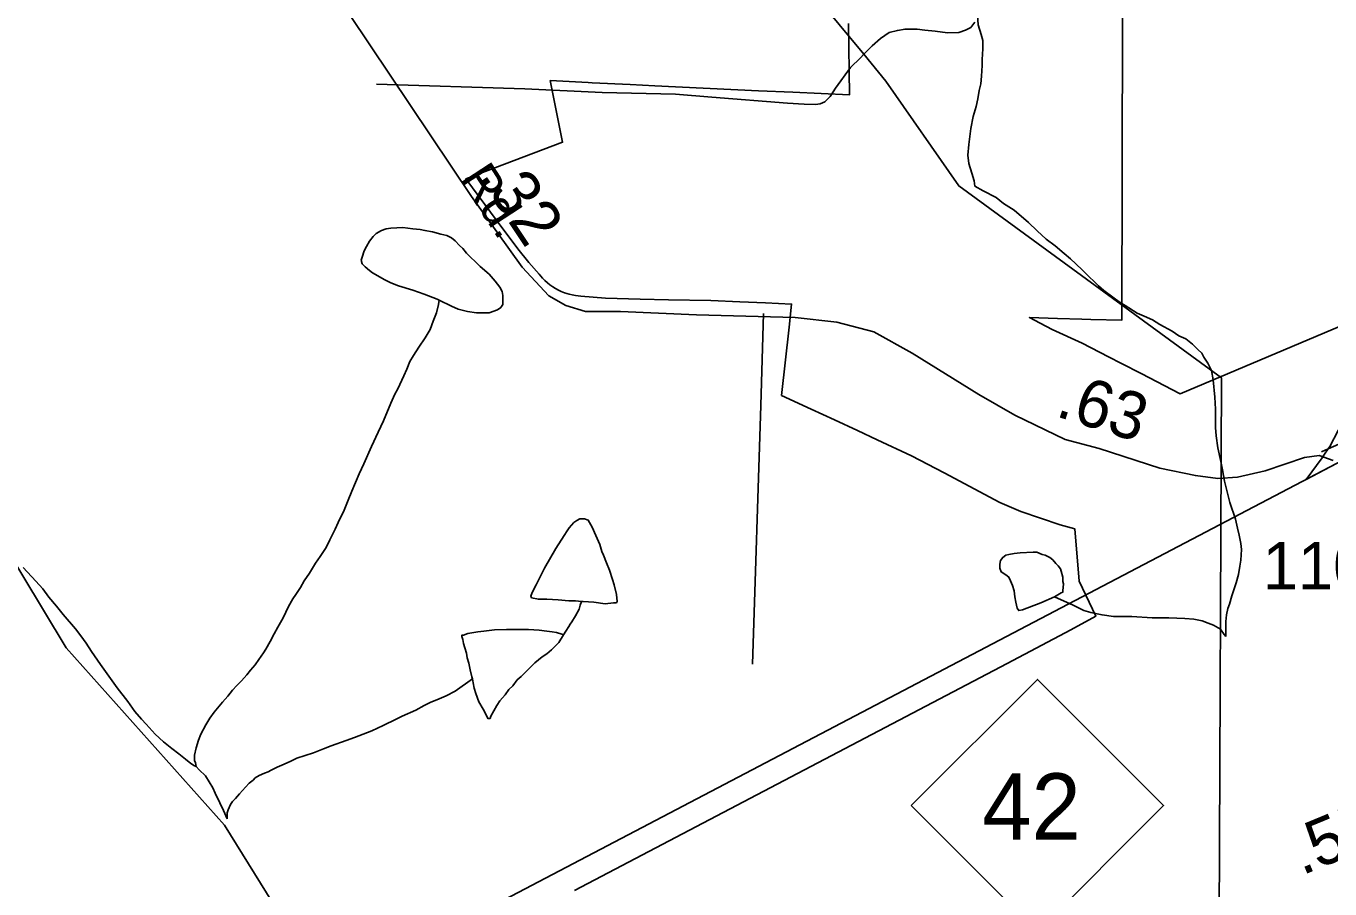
# Model space of a CAD drawing. Extents: x 2001466 to 2224147, y 644118 to 847247.
# Drawn here: x 2052213 to 2055654, y 667157 to 669433 of the extents above; entities that cross this region are included whole.
import ezdxf

# ---------------------------------------------------------------- set-up
doc = ezdxf.new("R2010")
doc.units = 0
for name, color, linetype in [('Exist Boundary Political City Limit New', 7, 'Continuous'), ('Exist Hydrographic Creek Single Shore', 7, 'Continuous'), ('Exist Hydrographic Misc Water Feature', 7, 'Continuous'), ('Exist Railroad Mainline', 7, 'Continuous'), ('Exist Railroad Siding', 7, 'Continuous'), ('Exist Road Non-System Type 51', 7, 'Continuous'), ('Exist Road Primary NC Service Mileage Hundredths English Label', 7, 'Continuous'), ('Exist Road Primary NC Shield CELL', 7, 'Continuous'), ('Exist Road Primary NC Shield Number Label', 7, 'Continuous'), ('Exist Road Secondary Mileage Hundredths English Label', 7, 'Continuous'), ('Exist Road Secondary Type 51 Attributed', 7, 'Continuous'), ('Exist Road Secondary Type 51 Label', 7, 'Continuous'), ('Exist Road Secondary Type 51 Number Label', 7, 'Continuous'), ('Map Preparation Boundary City Limit Buffer Line', 7, 'Continuous')]:
    doc.layers.add(name, color=color, linetype=linetype)

msp = doc.modelspace()

# ---------------------------------------------------------------- linework, layer by layer
at = {"layer": 'Exist Boundary Political City Limit New'}
for points in [[(2055701.8, 668649.8), (2055258.9, 668463.2), (2055156.2, 668516.1), (2055104.1, 668543), (2055069.6, 668560.8), (2055000, 668596.4), (2054921.2, 668632.2), (2054889.4, 668649.1), (2054860.8, 668663.9), (2054935.2, 668661.9), (2054999.6, 668660.2), (2055023.4, 668659.4), (2055104.4, 668657.1), (2055105.8, 669052.5), (2055106.2, 669457.1)], [(2054383.1, 669440), (2054385.9, 669251.4), (2054237, 669258.4), (2054146, 669262.7), (2053872, 669275.7), (2053807.2, 669278.8), (2053707.2, 669283.6), (2053696.8, 669284), (2053596.4, 669289.1), (2053629.1, 669126.5), (2053373.8, 669030.4), (2053456.2, 668918.2), (2053510.9, 668845.7), (2053540.2, 668809.4), (2053566.8, 668778.3), (2053576, 668767.7), (2053582, 668761.8), (2053588.8, 668755.8), (2053595.5, 668750.5), (2053602.8, 668745.5), (2053610.1, 668740.9), (2053617.8, 668736.7), (2053625.5, 668733.1), (2053633.9, 668729.7), (2053646.2, 668725.8), (2053654.6, 668723.8), (2053663.2, 668722.2), (2053676.9, 668720.7), (2053741.8, 668715), (2053833.8, 668712.4), (2053908.2, 668710.8), (2054020.4, 668709.4), (2054096.8, 668705.5), (2054164.5, 668703.1), (2054233.2, 668699.8), (2054226.8, 668638.8), (2054207, 668458.8), (2054285.2, 668422.3), (2054346.1, 668394.1), (2054407.1, 668365.7), (2054459, 668341.6), (2054549.8, 668299.6), (2054635.6, 668254.1), (2054782.9, 668176.1), (2054838.4, 668152.8), (2054942.1, 668117.1), (2054980.4, 668106.4), (2054991.9, 667968.2), (2055036.6, 667876.4), (2054970, 667839.8), (2054801.8, 667751.5), (2053660.4, 667152.6)]]:
    msp.add_lwpolyline(points, dxfattribs=at)
at = {"layer": 'Exist Hydrographic Creek Single Shore'}
msp.add_lwpolyline([(2053017.7, 666872.7), (2052736.4, 667325.2), (2052319.3, 667793), (2052143.4, 668082), (2051868.4, 668350), (2051451.4, 668630.9), (2051117.3, 668781.9), (2050292.4, 668952.9), (2050134.3, 669028.3), (2049975.4, 669271), (2049847.4, 669402.6)], dxfattribs=at)
at = {"layer": 'Exist Hydrographic Misc Water Feature'}
for points in [[(2054423.7, 669358.6), (2054098.4, 669751.6), (2053823.4, 669954), (2053598.5, 670168.5), (2053547.4, 670310.7), (2053489.4, 670528.5), (2053363.5, 670609.7), (2052988.4, 670633.8)], [(2054761.9, 669556.8), (2054739.8, 669514.7), (2054729.9, 669490.7), (2054726, 669476.7), (2054724, 669462.7), (2054726, 669436.7), (2054734, 669410.7), (2054738.1, 669394.8), (2054738.1, 669372.8), (2054736.3, 669344.8), (2054736.3, 669328.8), (2054734.2, 669300.8), (2054732.4, 669280.8), (2054728.3, 669262.8), (2054724.4, 669240.8), (2054720.5, 669220.8), (2054712.5, 669194.7), (2054706.6, 669162.7), (2054700.6, 669120.7), (2054698.8, 669092.7), (2054700.8, 669070.7), (2054708.8, 669044.8), (2054715, 669024.8), (2054716.8, 669010.8)], [(2055335.1, 668528.9), (2054674.4, 669011.5), (2054482.4, 669287.7), (2054423.7, 669358.6)], [(2054716.8, 669010.8), (2054739, 668998.8), (2054772.8, 668980.9), (2054792.9, 668964.9), (2054820.8, 668947), (2054858.9, 668915.1), (2054881.1, 668893.1), (2054905.1, 668871.2), (2054929, 668853.2), (2054953, 668833.3), (2054969, 668819.3), (2054983.2, 668805.4), (2055001.2, 668789.4), (2055017.2, 668773.4), (2055033.2, 668757.4), (2055043.3, 668747.5), (2055057.2, 668735.5), (2055081.2, 668717.5), (2055097.4, 668705.6), (2055113.4, 668695.6), (2055145.4, 668675.7), (2055163.4, 668667.7), (2055185.4, 668657.7), (2055205.5, 668645.8), (2055237.4, 668627.8), (2055255.5, 668615.8), (2055273.5, 668607.9), (2055291.6, 668593.9), (2055305.5, 668580), (2055315.6, 668570), (2055321.5, 668560), (2055331.6, 668544.1), (2055341.6, 668524), (2055345.5, 668500), (2055349.8, 668454.1), (2055351.7, 668422.1), (2055351.9, 668398.1), (2055351.9, 668374.1), (2055353.9, 668352.1), (2055358, 668320.1), (2055366, 668284.1), (2055370.1, 668262.2), (2055376.1, 668232.2), (2055390.2, 668176.2), (2055404.4, 668132.2), (2055410.3, 668108.2), (2055414.4, 668090.2), (2055418.5, 668068.3), (2055420.6, 668052.3), (2055418.5, 668024.3), (2055416.5, 668008.3), (2055412.6, 667986.3), (2055406.6, 667964.3), (2055398.6, 667940.2), (2055394.7, 667930.2), (2055388.8, 667908.3), (2055384.7, 667896.3), (2055380.8, 667880.2), (2055379.6, 667862.3), (2055379.4, 667852.2), (2055379.6, 667862.3), (2055379.4, 667852.2), (2055378.9, 667822.2)], [(2053303.6, 668710.2), (2053335.6, 668694.3), (2053353.8, 668686.3), (2053377.8, 668680.4), (2053401.8, 668676.4), (2053411.7, 668676.4), (2053435.6, 668676.4), (2053457.6, 668684.5), (2053465.6, 668690.5), (2053471.5, 668698.5), (2053471.5, 668708.5), (2053471.5, 668722.5), (2053469.7, 668732.5), (2053463.5, 668744.5), (2053451.4, 668760.5), (2053435.4, 668778.4), (2053411.5, 668798.4), (2053399.6, 668810.4), (2053385.4, 668824.3), (2053375.4, 668834.3), (2053365.3, 668846.3), (2053357.3, 668854.3), (2053345.4, 668866.3), (2053335.4, 668874.3), (2053323.3, 668880.2), (2053307.3, 668884.2), (2053285.3, 668890.1), (2053265.5, 668894.1), (2053253.4, 668896), (2053233.5, 668898), (2053207.4, 668902), (2053175.4, 668899.9), (2053163.3, 668897.9), (2053151.4, 668893.9), (2053137.3, 668885.9), (2053129.3, 668877.9), (2053119.5, 668865.8), (2053111.5, 668851.8), (2053105.5, 668839.8), (2053099.6, 668823.8), (2053097.5, 668815.8), (2053099.6, 668805.8), (2053107.6, 668797.8), (2053119.5, 668787.9), (2053127.5, 668781.9), (2053159.6, 668763.9), (2053175.6, 668755.9), (2053195.5, 668748), (2053233.7, 668736.1), (2053263.6, 668726.1), (2053297.6, 668712.2), (2053303.6, 668710.2)], [(2053303.6, 668710.2), (2053301.5, 668698.2), (2053295.8, 668676.2), (2053287.8, 668654.2), (2053279.8, 668632.2), (2053265.9, 668610.2), (2053249.9, 668586.1), (2053235.9, 668564.1), (2053226.1, 668548.1), (2053218.1, 668528.1), (2053210.1, 668510.1), (2053194.1, 668476), (2053186.1, 668462.1), (2053176.1, 668438), (2053156.2, 668392), (2053142.4, 668362), (2053124.4, 668323.9), (2053104.5, 668277.9), (2053092.4, 668251.9), (2053072.7, 668205.9), (2053062.7, 668181.9), (2053050.8, 668151.9), (2053044.8, 668139.8), (2053036.8, 668123.8), (2053028.8, 668105.8), (2053014.9, 668077.8), (2053004.8, 668057.8), (2052989, 668033.7), (2052976.9, 668015.8), (2052961, 667989.7), (2052947, 667969.7), (2052937.2, 667951.7), (2052925.1, 667933.7), (2052917.1, 667921.6), (2052905.2, 667901.6), (2052891.2, 667871.6), (2052877.3, 667847.6), (2052867.4, 667829.6), (2052857.4, 667809.6), (2052845.5, 667789.6), (2052839.6, 667779.5), (2052827.5, 667761.5), (2052817.4, 667747.5), (2052805.5, 667733.5), (2052795.7, 667721.5), (2052781.5, 667705.4), (2052769.6, 667693.4), (2052757.5, 667681.4), (2052745.6, 667665.4), (2052731.7, 667649.4), (2052709.8, 667623.3), (2052697.7, 667607.3), (2052687.8, 667589.3), (2052673.9, 667565.3), (2052667.9, 667549.3), (2052662, 667529.2), (2052657.9, 667509.2), (2052657.9, 667495.2), (2052659.9, 667489.2), (2052662, 667479.2)], [(2055607.1, 666261.8), (2055604.3, 666282.6), (2055378.3, 666930.3), (2055361.3, 667071.7), (2055367.4, 668505.3), (2055335.1, 668528.9)], [(2053679, 667915.1), (2053663.1, 667917), (2053645, 667917), (2053616.9, 667919), (2053587, 667920.9), (2053565, 667920.8), (2053547, 667924.8), (2053544.9, 667928.8), (2053549, 667938.8), (2053558.9, 667958.8), (2053573, 667986.8), (2053580.8, 668002.9), (2053610.8, 668054.9), (2053632.7, 668089), (2053640.7, 668101), (2053646.6, 668109), (2053658.5, 668123), (2053666.5, 668129), (2053674.5, 668133), (2053686.6, 668133), (2053696.7, 668129.1), (2053706.7, 668111.1), (2053716.8, 668089.1), (2053726.8, 668065.1), (2053732.8, 668047.1), (2053736.9, 668037.1), (2053744.9, 668017.1), (2053752.9, 667997.2), (2053760.9, 667973.2), (2053765, 667959.2), (2053770.9, 667933.2), (2053773, 667915.3), (2053770.9, 667911.3), (2053762.9, 667911.2), (2053741, 667909.2), (2053711, 667913.1), (2053682.9, 667915.1), (2053679, 667915.1)], [(2054926.8, 667927.4), (2054890.9, 667911.3), (2054842.9, 667893.2), (2054832.9, 667891.2), (2054828.8, 667897.2), (2054824.9, 667913.2), (2054822.8, 667927.2), (2054820.8, 667943.2), (2054816.7, 667957.2), (2054810.7, 667969.2), (2054806.6, 667979.2), (2054798.6, 667985.2), (2054786.7, 667993.1), (2054782.6, 668003.1), (2054782.6, 668013.1), (2054784.7, 668023.1), (2054790.6, 668031.1), (2054798.6, 668037.1), (2054806.6, 668039.2), (2054820.6, 668041.2), (2054836.6, 668043.2), (2054870.6, 668045.3), (2054880.7, 668045.3), (2054894.6, 668039.3), (2054902.6, 668037.3), (2054914.5, 668031.3), (2054922.7, 668025.3), (2054930.7, 668015.3), (2054936.6, 668009.4), (2054942.6, 668001.4), (2054944.6, 667995.4), (2054948.7, 667979.4), (2054948.7, 667967.4), (2054950.8, 667961.4), (2054948.7, 667943.4), (2054948.7, 667939.4), (2054944.6, 667937.4), (2054926.8, 667927.4)], [(2052205.1, 668004.3), (2052239.2, 667968.3), (2052257.2, 667948.4), (2052273.2, 667926.4), (2052293.3, 667902.5), (2052311.3, 667880.5), (2052343.5, 667842.6), (2052357.5, 667824.6), (2052371.4, 667804.7), (2052385.6, 667782.7), (2052409.6, 667748.7), (2052453.7, 667686.8), (2052481.7, 667650.9), (2052499.8, 667624.9), (2052517.8, 667604.9), (2052529.9, 667591), (2052553.9, 667565.1), (2052575.9, 667545.1), (2052598, 667527.1), (2052616.1, 667513.2), (2052633.9, 667499.2), (2052648, 667487.2), (2052657.9, 667481.2), (2052662, 667479.2)], [(2053679, 667915.1), (2053675.1, 667905.1), (2053673.1, 667895.1), (2053663.1, 667877), (2053653, 667861), (2053649.1, 667855), (2053645, 667849), (2053637.2, 667837), (2053631.3, 667827)], [(2054926.8, 667927.4), (2054976.8, 667905.5), (2055004.9, 667891.5), (2055022.8, 667885.6), (2055052.9, 667879.6), (2055082.8, 667875.7), (2055130.8, 667875.8), (2055184.7, 667871.9), (2055228.8, 667872), (2055270.9, 667870.1), (2055294.9, 667868.1), (2055316.8, 667864.1), (2055332.8, 667858.2), (2055346.7, 667852.2), (2055364.8, 667842.2), (2055374.8, 667828.2), (2055378.9, 667822.2)], [(2053391.6, 667710.6), (2053389.5, 667716.6), (2053385.4, 667734.6), (2053381.3, 667752.6), (2053377.4, 667766.5), (2053375.4, 667778.5), (2053371.3, 667792.5), (2053367.4, 667804.5), (2053365.3, 667814.5), (2053363.3, 667822.5), (2053363.3, 667826.5), (2053367.2, 667826.5), (2053379.3, 667830.5), (2053405.3, 667834.6), (2053421.3, 667836.6), (2053449.2, 667840.6), (2053481.2, 667840.7), (2053511.3, 667840.7), (2053539.2, 667840.8), (2053567.3, 667838.9), (2053587.2, 667836.9), (2053601.1, 667835), (2053613.2, 667833), (2053627.2, 667829), (2053631.3, 667827)], [(2053631.3, 667827), (2053619.2, 667807), (2053599.3, 667787), (2053587.4, 667777), (2053575.3, 667768.9), (2053565.2, 667760.9), (2053555.4, 667752.9), (2053535.3, 667732.8), (2053519.5, 667716.8), (2053509.5, 667708.7), (2053497.4, 667692.7), (2053487.5, 667682.8), (2053477.5, 667668.8), (2053463.5, 667652.7), (2053455.5, 667640.7), (2053447.5, 667626.7), (2053439.5, 667612.7), (2053437.5, 667606.7), (2053431.5, 667606.6), (2053429.5, 667610.6), (2053419.7, 667630.6), (2053407.6, 667650.6), (2053399.6, 667672.5), (2053395.5, 667686.6), (2053393.4, 667700.6), (2053391.6, 667710.6)], [(2053391.6, 667710.6), (2053345.4, 667678.5), (2053321.6, 667666.4), (2053303.6, 667658.5), (2053279.6, 667648.4), (2053263.6, 667640.3), (2053241.7, 667628.3), (2053205.8, 667612.3), (2053189.8, 667604.2), (2053155.8, 667588.1), (2053125.8, 667574.1), (2053079.9, 667556), (2053057.7, 667548), (2053017.8, 667533.9), (2052997.9, 667525.9), (2052971.8, 667515.8), (2052927.9, 667501.7), (2052911.9, 667493.7), (2052893.9, 667485.7), (2052876.1, 667477.6), (2052859.9, 667469.6), (2052851.9, 667465.6), (2052842, 667461.6), (2052828.1, 667455.6), (2052818, 667449.6), (2052812.1, 667443.6), (2052802, 667435.5), (2052792, 667425.5), (2052776, 667407.5), (2052766.2, 667395.4), (2052758.2, 667387.4), (2052752.2, 667379.4), (2052746.3, 667365.4), (2052744.2, 667357.4), (2052744.2, 667341.4)], [(2052662, 667479.2), (2052670.2, 667471.2), (2052686.2, 667455.3), (2052696, 667439.3), (2052706.1, 667423.4), (2052712, 667409.4), (2052724.1, 667383.4), (2052734.2, 667363.4), (2052744.2, 667341.4)]]:
    msp.add_lwpolyline(points, dxfattribs=at)
at = {"layer": 'Exist Railroad Mainline'}
msp.add_line((2055671.2, 668278.9), (2055591, 668236.8), dxfattribs=at)
msp.add_lwpolyline([(2046464.5, 663426.2), (2046524.6, 663459.1), (2048551.7, 664535.4), (2049194.6, 664876.7), (2049524.4, 665051.8), (2049557.2, 665070.3), (2052622.8, 666680.7), (2055671.2, 668278.9), (2056997.6, 668963.3), (2058840.6, 669936.5)], dxfattribs=at)
at = {"layer": 'Exist Railroad Siding'}
for points in [[(2055713.4, 668431.9), (2055675.4, 668365.9), (2055653.6, 668324), (2055649.3, 668317.5), (2055639.9, 668303.6)], [(2055639.9, 668303.6), (2055633.4, 668293.8), (2055591, 668236.8)]]:
    msp.add_lwpolyline(points, dxfattribs=at)
at = {"layer": 'Exist Road Non-System Type 51'}
for p, q in [((2054159.3, 668674.9), (2054151.8, 668432)), ((2054151.8, 668432), (2054130.5, 667749.5)), ((2055631.9, 668309.9), (2055649.3, 668317.5))]:
    msp.add_line(p, q, dxfattribs=at)
for points in [[(2054717, 669443.6), (2054706.7, 669429.8), (2054692.5, 669422.1), (2054674.4, 669416.4), (2054644.4, 669415.1), (2054612.5, 669419.7), (2054584.5, 669422.3), (2054564.6, 669424.7), (2054548.6, 669425), (2054532.6, 669425.3), (2054512.5, 669421.7), (2054490.4, 669416.2), (2054468.1, 669400.6), (2054445.7, 669381.1), (2054423.7, 669358.6)], [(2054423.7, 669358.6), (2054415.1, 669349.7), (2054388.6, 669324.2), (2054349.4, 669269), (2054335, 669247.3), (2054320.7, 669233.6), (2054308.6, 669227.9), (2054296.6, 669226.1), (2054266.6, 669226.7), (2054222.6, 669229.6), (2054023, 669245.7), (2053927.1, 669253.6), (2053733.2, 669257.6), (2053529.4, 669267.7), (2053137.6, 669279.6)], [(2055649.3, 668317.5), (2055756.1, 668364), (2055874.9, 668434.2), (2055923.5, 668488.2), (2055993.7, 668779.9)]]:
    msp.add_lwpolyline(points, dxfattribs=at)
at = {"layer": 'Exist Road Primary NC Shield CELL'}
msp.add_lwpolyline([(2054549.1, 667376.3), (2054882.1, 667709.3), (2055215.1, 667376.3), (2054882.1, 667043.3)], close=True, dxfattribs=at)
at = {"layer": 'Exist Road Secondary Type 51 Attributed'}
msp.add_lwpolyline([(2053066.3, 669463.6), (2053388.6, 668983.3), (2053522.6, 668797.4), (2053592.3, 668721.3), (2053637.7, 668695.9), (2053689.4, 668680.1), (2053781.8, 668680.1), (2053982.3, 668671.6), (2054242.5, 668664.3), (2054352.3, 668651.6), (2054450.5, 668626.2), (2054551.8, 668570.2), (2054727.6, 668461.4), (2054822.6, 668406.5), (2054955.6, 668342.1), (2055045.3, 668318.8), (2055205.2, 668267.1), (2055299.2, 668247), (2055358.3, 668239.6), (2055410, 668242.8), (2055482.8, 668259.7), (2055587.3, 668294.5), (2055625.3, 668299.8), (2055662.3, 668287.1)], dxfattribs=at)
at = {"layer": 'Map Preparation Boundary City Limit Buffer Line'}
for points in [[(2055701.8, 668649.8), (2055258.9, 668463.2), (2055156.2, 668516.1), (2055104.1, 668543), (2055069.6, 668560.8), (2055000, 668596.4), (2054921.2, 668632.2), (2054889.4, 668649.1), (2054860.8, 668663.9), (2054935.2, 668661.9), (2054999.6, 668660.2), (2055023.4, 668659.4), (2055104.4, 668657.1), (2055105.8, 669052.5), (2055106.2, 669457.1)], [(2054383.1, 669440), (2054385.9, 669251.4), (2054237, 669258.4), (2054146, 669262.7), (2053872, 669275.7), (2053807.2, 669278.8), (2053707.2, 669283.6), (2053696.8, 669284), (2053596.4, 669289.1), (2053629.1, 669126.5), (2053373.8, 669030.4), (2053456.2, 668918.2), (2053510.9, 668845.7), (2053540.2, 668809.4), (2053566.8, 668778.3), (2053576, 668767.7), (2053582, 668761.8), (2053588.8, 668755.8), (2053595.5, 668750.5), (2053602.8, 668745.5), (2053610.1, 668740.9), (2053617.8, 668736.7), (2053625.5, 668733.1), (2053633.9, 668729.7), (2053646.2, 668725.8), (2053654.6, 668723.8), (2053663.2, 668722.2), (2053676.9, 668720.7), (2053741.8, 668715), (2053833.8, 668712.4), (2053908.2, 668710.8), (2054020.4, 668709.4), (2054096.8, 668705.5), (2054164.5, 668703.1), (2054233.2, 668699.8), (2054226.8, 668638.8), (2054207, 668458.8), (2054285.2, 668422.3), (2054346.1, 668394.1), (2054407.1, 668365.7), (2054459, 668341.6), (2054549.8, 668299.6), (2054635.6, 668254.1), (2054782.9, 668176.1), (2054838.4, 668152.8), (2054942.1, 668117.1), (2054980.4, 668106.4), (2054991.9, 667968.2), (2055036.6, 667876.4), (2054970, 667839.8), (2054801.8, 667751.5), (2053660.4, 667152.6)]]:
    msp.add_lwpolyline(points, dxfattribs=at)

# ---------------------------------------------------------------- texts
at = {"layer": 'Exist Road Primary NC Service Mileage Hundredths English Label'}
msp.add_text('.55', height=125, rotation=22.4446, dxfattribs=at).set_placement((2055580, 667191.5))
at = {"layer": 'Exist Road Primary NC Shield Number Label'}
msp.add_text('42', height=175, dxfattribs=at).set_placement((2054736.3, 667286.6))
at = {"layer": 'Exist Road Secondary Mileage Hundredths English Label'}
for s, rotation, p in [('.32', 303.7991, (2053404.9, 669036.5)), ('.63', 342.3315, (2054926.6, 668404.9))]:
    msp.add_text(s, height=125, rotation=rotation, dxfattribs=at).set_placement(p)
at = {"layer": 'Exist Road Secondary Type 51 Label'}
msp.add_text('Rd.', height=95, rotation=303.0911, dxfattribs=at).set_placement((2053355.4, 669030.4))
at = {"layer": 'Exist Road Secondary Type 51 Number Label'}
msp.add_text('1105', height=125, dxfattribs=at).set_placement((2055476.6, 667947))

doc.saveas('drawing.dxf')
